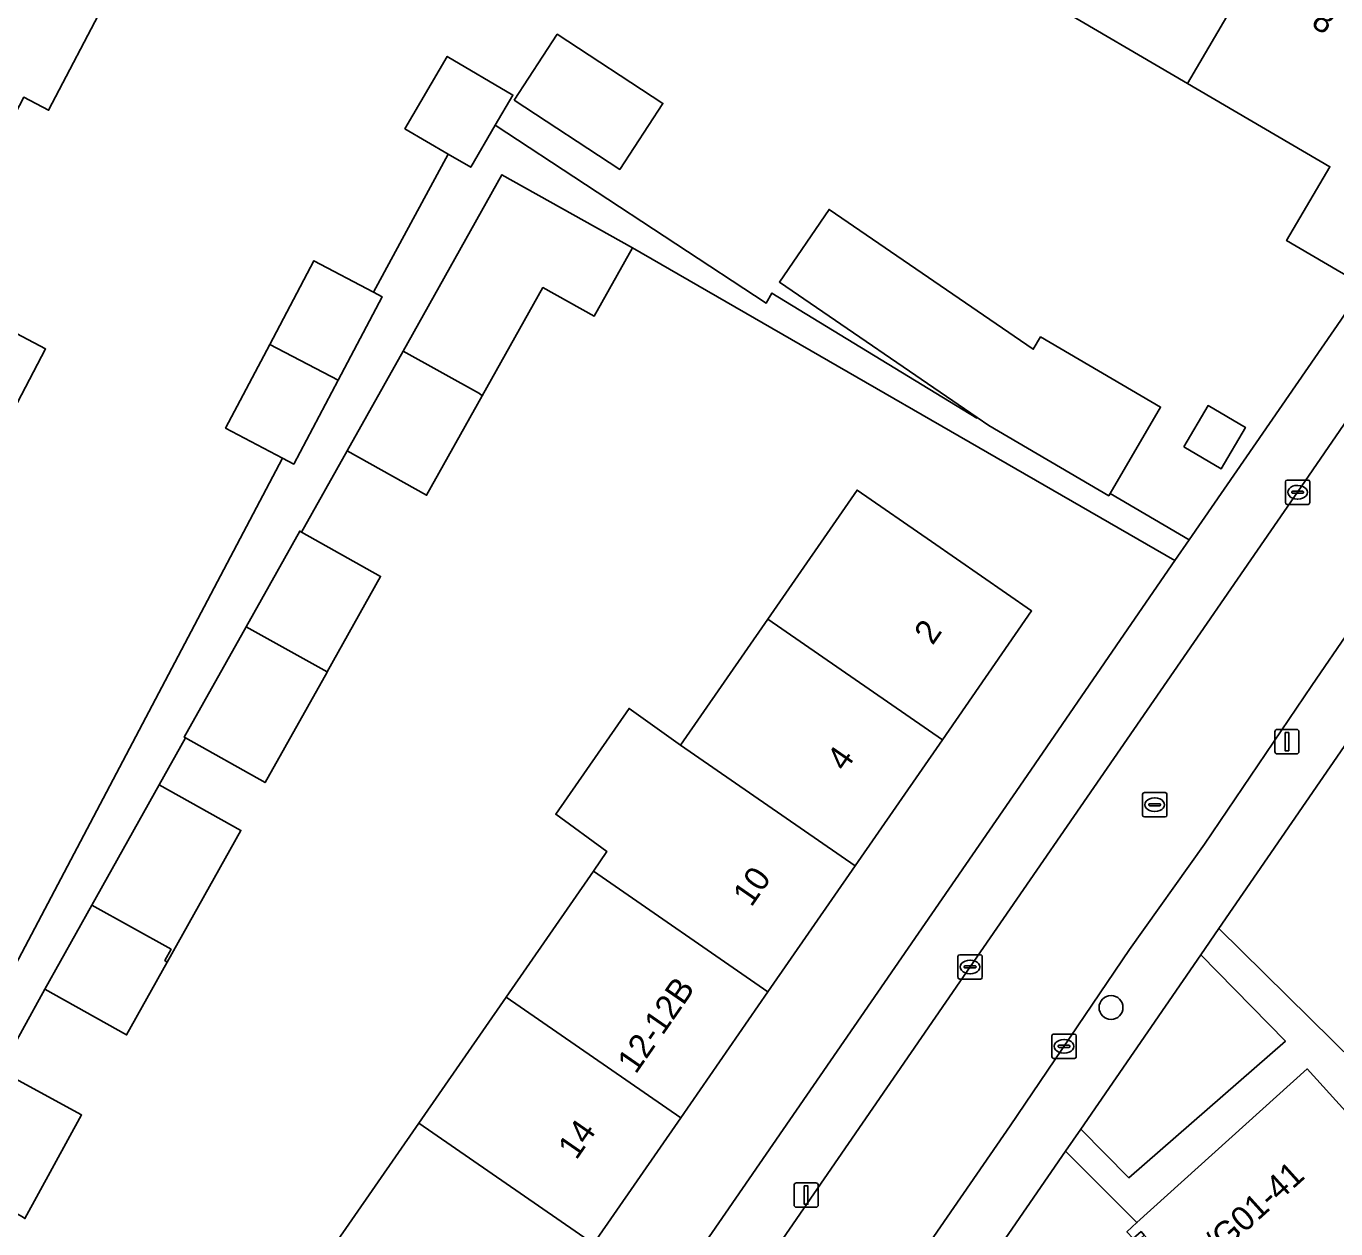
# Model space of a CAD drawing. Extents: x 160349 to 161355, y 381727 to 382854.
# Drawn here: x 160836.8 to 160890.5, y 382044.3 to 382093.6 of the extents above; entities that cross this region are included whole.
import ezdxf

# ---------------------------------------------------------------- set-up
doc = ezdxf.new("R2010")
doc.units = 0
for name, color, linetype in [('IMGEO_Boom', 7, 'Continuous'), ('IMGEO_Erf', 7, 'Continuous'), ('IMGEO_Groenvoorziening', 7, 'Continuous'), ('IMGEO_Kolk', 7, 'Continuous'), ('IMGEO_Lichtmast', 7, 'Continuous'), ('IMGEO_Pand', 7, 'Continuous'), ('IMGEO_Pand_nummerreeks', 7, 'Continuous'), ('IMGEO_Rijbaan_lokaal_open', 7, 'Continuous'), ('IMGEO_Rioolput', 7, 'Continuous'), ('IMGEO_Voetpad_open', 7, 'Continuous')]:
    doc.layers.add(name, color=color, linetype=linetype)

msp = doc.modelspace()

# ---------------------------------------------------------------- linework, layer by layer
at = {"layer": 'IMGEO_Boom'}
msp.add_circle((160881.263, 382053.407), 0.489, dxfattribs=at)
at = {"layer": 'IMGEO_Erf'}
for points in [[(160828.644, 382105.359), (160839.235, 382099.82), (160840.979, 382098.908), (160841.554, 382097.53), (160840.049, 382094.652), (160837.714, 382090.187), (160836.694, 382090.72)], [(160894.194, 382094.645), (160892.301, 382091.408), (160894.868, 382089.907), (160895.433, 382089.577), (160891.222, 382082.372), (160890.937, 382082.539), (160891.31, 382083.178), (160890.54, 382083.628), (160888.463, 382084.842), (160890.235, 382087.873), (160885.919, 382090.396), (160884.403, 382091.282), (160878.701, 382094.616)], [(160848.59, 382084.018), (160851.025, 382082.733), (160854.087, 382088.394), (160852.318, 382089.43), (160854.052, 382092.392), (160856.749, 382090.813), (160856.025, 382089.578), (160867.129, 382082.286), (160867.364, 382082.695), (160875.757, 382077.566), (160875.777, 382077.589), (160867.667, 382083.145), (160869.707, 382086.124), (160878.078, 382080.389), (160878.374, 382080.895), (160883.294, 382078.019), (160881.225, 382074.478), (160884.468, 382072.583), (160886.418, 382075.41), (160890.681, 382081.588), (160891.222, 382082.372), (160892.908, 382084.909), (160896.288, 382089.767), (160898.701, 382093.297)], [(160882.102, 382069.151), (160883.88, 382071.73), (160861.644, 382084.547), (160860.073, 382081.743), (160857.976, 382082.918), (160855.49, 382078.482), (160853.206, 382074.407), (160849.954, 382076.23), (160848.084, 382072.892), (160851.323, 382071.077), (160849.131, 382067.164), (160849.125, 382067.154), (160846.587, 382062.624), (160843.318, 382064.456), (160842.243, 382062.537), (160845.594, 382060.663), (160842.578, 382055.268), (160840.909, 382052.283), (160837.557, 382054.157), (160835.733, 382050.826), (160839.066, 382049.001), (160836.741, 382044.754)], [(160834.328, 382051.343), (160847.298, 382075.927), (160844.969, 382077.156), (160846.778, 382080.583), (160848.59, 382084.018)], [(160833.72, 382082.44), (160837.592, 382080.403), (160835.263, 382075.977)], [(160849.315, 382043.503), (160852.891, 382048.667), (160856.467, 382053.832), (160860.043, 382058.997), (160860.598, 382059.799), (160858.504, 382061.331), (160861.506, 382065.666), (160863.619, 382064.162), (160867.195, 382069.326), (160870.856, 382074.614), (160873.898, 382072.508), (160878.009, 382069.663), (160874.349, 382064.374), (160870.774, 382059.209), (160867.2, 382054.044), (160863.624, 382048.878), (160860.049, 382043.712)], [(160804.86, 381957.022), (160809.509, 381963.746), (160815.556, 381972.499), (160830.024, 381993.552), (160843.658, 382013.325), (160856.447, 382031.904), (160864.216, 382043.168), (160877.531, 382062.485), (160882.102, 382069.151)]]:
    msp.add_lwpolyline(points, dxfattribs=at)
for points in [[(160856.791, 382090.604), (160858.56, 382093.305), (160862.896, 382090.467), (160861.127, 382087.766)], [(160884.254, 382076.388), (160885.242, 382078.079), (160886.772, 382077.184), (160885.784, 382075.494)]]:
    msp.add_lwpolyline(points, close=True, dxfattribs=at)
at = {"layer": 'IMGEO_Groenvoorziening'}
for points in [[(160895.379, 382070.732), (160885.684, 382056.644), (160893.142, 382049.287)], [(160876.819, 382030.108), (160878.78, 382040.608), (160882.622, 382044.08), (160882.494, 382044.222), (160882.171, 382043.93), (160881.914, 382044.215), (160882.326, 382044.588), (160879.4, 382047.514), (160856.025, 382013.549), (160862.42, 382009.21), (160864.718, 382006.576), (160868.779, 382010.311), (160869.404, 382012.942), (160868.801, 382014.089), (160865.741, 382012.48), (160864.478, 382014.847)]]:
    msp.add_lwpolyline(points, dxfattribs=at)
msp.add_lwpolyline([(160881.997, 382046.425), (160888.414, 382052.033), (160884.945, 382055.57), (160880.026, 382048.423)], close=True, dxfattribs=at)
at = {"layer": 'IMGEO_Kolk'}
for p, q in [((160888.411, 382074.102), (160888.411, 382074.954)), ((160888.486, 382075.028), (160889.338, 382075.028)), ((160888.899, 382074.808), (160888.924, 382074.808)), ((160889.412, 382074.954), (160889.412, 382074.102)), ((160888.67, 382074.522), (160888.67, 382074.534)), ((160889.108, 382074.485), (160888.71, 382074.485)), ((160888.713, 382074.571), (160889.111, 382074.571)), ((160888.922, 382074.248), (160888.897, 382074.248)), ((160889.154, 382074.534), (160889.154, 382074.522)), ((160889.338, 382074.028), (160888.486, 382074.028)), ((160874.986, 382054.643), (160874.986, 382055.495)), ((160875.061, 382055.569), (160875.913, 382055.569)), ((160875.474, 382055.349), (160875.499, 382055.349)), ((160875.987, 382055.495), (160875.987, 382054.643)), ((160875.245, 382055.063), (160875.245, 382055.075)), ((160875.683, 382055.026), (160875.285, 382055.026)), ((160875.288, 382055.112), (160875.686, 382055.112)), ((160875.497, 382054.789), (160875.472, 382054.789)), ((160875.729, 382055.075), (160875.729, 382055.063)), ((160875.913, 382054.569), (160875.061, 382054.569)), ((160878.837, 382051.389), (160878.837, 382052.241)), ((160878.912, 382052.315), (160879.764, 382052.315)), ((160879.325, 382052.095), (160879.35, 382052.095)), ((160879.838, 382052.241), (160879.838, 382051.389)), ((160879.096, 382051.809), (160879.096, 382051.821)), ((160879.534, 382051.772), (160879.136, 382051.772)), ((160879.139, 382051.858), (160879.537, 382051.858)), ((160879.348, 382051.535), (160879.323, 382051.535)), ((160879.58, 382051.821), (160879.58, 382051.809)), ((160879.764, 382051.315), (160878.912, 382051.315))]:
    msp.add_line(p, q, dxfattribs=at)
for points in [[(160888.411, 382074.102), (160888.411, 382074.954)], [(160888.486, 382075.028), (160889.338, 382075.028)], [(160889.412, 382074.954), (160889.412, 382074.102)], [(160889.338, 382074.028), (160888.486, 382074.028)], [(160874.986, 382054.643), (160874.986, 382055.495)], [(160875.061, 382055.569), (160875.913, 382055.569)], [(160875.987, 382055.495), (160875.987, 382054.643)], [(160875.913, 382054.569), (160875.061, 382054.569)], [(160878.837, 382051.389), (160878.837, 382052.241)], [(160878.912, 382052.315), (160879.764, 382052.315)], [(160879.838, 382052.241), (160879.838, 382051.389)], [(160879.764, 382051.315), (160878.912, 382051.315)]]:
    msp.add_lwpolyline(points, dxfattribs=at)
for centre, radius, start, end in [((160888.488, 382074.952), 0.0765, 91.552, 178.448), ((160888.488, 382074.952), 0.0765, 91.552, 178.448), ((160889.336, 382074.952), 0.0765, 1.552, 88.448), ((160889.336, 382074.952), 0.0765, 1.552, 88.448), ((160888.488, 382074.104), 0.0765, 181.552, 268.448), ((160888.488, 382074.104), 0.0765, 181.552, 268.448), ((160888.71, 382074.531), 0.0403, 85.8775, 175.7526), ((160888.707, 382074.521), 0.0366, 178.938, 274.7102), ((160889.111, 382074.528), 0.043, 264.8664, 352.4533), ((160889.115, 382074.533), 0.0386, 1.7309, 96.639), ((160889.336, 382074.104), 0.0765, 271.552, 358.448), ((160889.336, 382074.104), 0.0765, 271.552, 358.448), ((160875.063, 382055.493), 0.0765, 91.552, 178.448), ((160875.063, 382055.493), 0.0765, 91.552, 178.448), ((160875.911, 382055.493), 0.0765, 1.552, 88.448), ((160875.911, 382055.493), 0.0765, 1.552, 88.448), ((160875.285, 382055.072), 0.0403, 85.8775, 175.7526), ((160875.282, 382055.062), 0.0366, 178.938, 274.7102), ((160875.686, 382055.069), 0.043, 264.8664, 352.4533), ((160875.69, 382055.074), 0.0386, 1.7309, 96.639), ((160875.063, 382054.645), 0.0765, 181.552, 268.448), ((160875.063, 382054.645), 0.0765, 181.552, 268.448), ((160875.911, 382054.645), 0.0765, 271.552, 358.448), ((160875.911, 382054.645), 0.0765, 271.552, 358.448), ((160878.914, 382052.239), 0.0765, 91.552, 178.448), ((160878.914, 382052.239), 0.0765, 91.552, 178.448), ((160879.762, 382052.239), 0.0765, 1.552, 88.448), ((160879.762, 382052.239), 0.0765, 1.552, 88.448), ((160879.136, 382051.818), 0.0403, 85.8775, 175.7526), ((160879.133, 382051.808), 0.0366, 178.938, 274.7102), ((160879.537, 382051.815), 0.043, 264.8664, 352.4533), ((160879.541, 382051.82), 0.0386, 1.7309, 96.639), ((160878.914, 382051.391), 0.0765, 181.552, 268.448), ((160878.914, 382051.391), 0.0765, 181.552, 268.448), ((160879.762, 382051.391), 0.0765, 271.552, 358.448), ((160879.762, 382051.391), 0.0765, 271.552, 358.448)]:
    msp.add_arc(centre, radius, start, end, dxfattribs=at)
for centre, major_axis, ratio, start_param, end_param in [((160888.898, 382074.528), (-0.387, 0.002), 0.722429, 4.712389, 7.853982), ((160888.923, 382074.528), (-0.39, 0.002), 0.717154, 1.570796, 4.712389), ((160875.473, 382055.069), (-0.387, 0.002), 0.722429, 4.712389, 7.853982), ((160875.498, 382055.069), (-0.39, 0.002), 0.717154, 1.570796, 4.712389), ((160879.324, 382051.815), (-0.387, 0.002), 0.722429, 4.712389, 7.853982), ((160879.349, 382051.815), (-0.39, 0.002), 0.717154, 1.570796, 4.712389)]:
    msp.add_ellipse(centre, major_axis=major_axis, ratio=ratio, start_param=start_param, end_param=end_param, dxfattribs=at)
at = {"layer": 'IMGEO_Lichtmast'}
for p, q in [((160887.978, 382063.904), (160887.978, 382064.704)), ((160887.978, 382064.704), (160887.978, 382063.904)), ((160888.078, 382064.804), (160888.868, 382064.804)), ((160888.868, 382064.804), (160888.078, 382064.804)), ((160888.968, 382064.704), (160888.968, 382063.904)), ((160888.968, 382063.904), (160888.968, 382064.704)), ((160888.868, 382063.804), (160888.078, 382063.804)), ((160888.078, 382063.804), (160888.868, 382063.804)), ((160868.37, 382046.216), (160869.16, 382046.216)), ((160869.16, 382046.216), (160868.37, 382046.216)), ((160868.27, 382045.316), (160868.27, 382046.116)), ((160868.27, 382046.116), (160868.27, 382045.316)), ((160869.26, 382046.116), (160869.26, 382045.316)), ((160869.26, 382045.316), (160869.26, 382046.116)), ((160869.16, 382045.216), (160868.37, 382045.216)), ((160868.37, 382045.216), (160869.16, 382045.216))]:
    msp.add_line(p, q, dxfattribs=at)
for points in [[(160888.398, 382064.679), (160888.548, 382064.679), (160888.548, 382063.929), (160888.398, 382063.929), (160888.398, 382064.679)], [(160868.69, 382046.091), (160868.84, 382046.091), (160868.84, 382045.341), (160868.69, 382045.341), (160868.69, 382046.091)]]:
    msp.add_lwpolyline(points, dxfattribs=at)
for centre, start, end in [((160888.078, 382064.704), 90, 180), ((160888.078, 382064.704), 90, 180), ((160888.868, 382064.704), 0, 90), ((160888.868, 382064.704), 360, 90), ((160888.078, 382063.904), 180, 270), ((160888.078, 382063.904), 180, 270), ((160888.868, 382063.904), 270, 0), ((160888.868, 382063.904), 270, 0), ((160868.37, 382046.116), 90, 180), ((160868.37, 382046.116), 90, 180), ((160869.16, 382046.116), 0, 90), ((160869.16, 382046.116), 360, 90), ((160868.37, 382045.316), 180, 270), ((160868.37, 382045.316), 180, 270), ((160869.16, 382045.316), 270, 0), ((160869.16, 382045.316), 270, 0)]:
    msp.add_arc(centre, 0.1, start, end, dxfattribs=at)
at = {"layer": 'IMGEO_Pand'}
for points in [[(160878.701, 382094.616), (160884.403, 382091.282), (160888.362, 382098.054), (160882.66, 382101.388)], [(160840.049, 382094.652), (160837.1, 382096.26), (160829.984, 382099.917), (160828.329, 382096.753), (160829.665, 382096.055), (160828.832, 382094.462), (160826.953, 382090.869), (160834.676, 382086.862), (160836.694, 382090.72), (160837.714, 382090.187)], [(160894.194, 382094.645), (160888.362, 382098.054), (160884.403, 382091.282), (160885.919, 382090.396), (160890.235, 382087.873), (160888.463, 382084.842), (160890.54, 382083.628), (160891.31, 382083.178), (160890.937, 382082.539), (160891.222, 382082.372), (160895.433, 382089.577), (160894.868, 382089.907), (160892.301, 382091.408)], [(160856.791, 382090.604), (160861.127, 382087.766), (160862.896, 382090.467), (160858.56, 382093.305)], [(160852.318, 382089.43), (160854.087, 382088.394), (160855.014, 382087.851), (160856.025, 382089.578), (160856.749, 382090.813), (160854.052, 382092.392)], [(160826.953, 382090.869), (160825.065, 382087.259), (160824.243, 382085.688), (160822.918, 382086.381), (160821.314, 382083.315), (160831.402, 382078.008), (160835.263, 382075.977), (160837.592, 382080.403), (160833.72, 382082.44), (160832.655, 382082.997), (160834.676, 382086.862)], [(160852.241, 382080.31), (160855.373, 382078.573), (160855.49, 382078.482), (160857.976, 382082.918), (160860.073, 382081.743), (160861.644, 382084.547), (160856.296, 382087.545)], [(160883.294, 382078.019), (160878.374, 382080.895), (160878.078, 382080.389), (160869.707, 382086.124), (160867.667, 382083.145), (160875.777, 382077.589), (160876.251, 382077.264), (160881.172, 382074.388), (160881.225, 382074.478)], [(160851.382, 382082.545), (160851.025, 382082.733), (160848.59, 382084.018), (160846.778, 382080.583), (160849.58, 382079.129)], [(160849.58, 382079.129), (160846.778, 382080.583), (160844.969, 382077.156), (160847.298, 382075.927), (160847.761, 382075.683)], [(160852.241, 382080.31), (160849.954, 382076.23), (160853.206, 382074.407), (160855.49, 382078.482), (160855.373, 382078.573)], [(160884.254, 382076.388), (160885.784, 382075.494), (160886.772, 382077.184), (160885.242, 382078.079)], [(160867.195, 382069.326), (160874.349, 382064.374), (160878.009, 382069.663), (160873.898, 382072.508), (160870.856, 382074.614)], [(160851.323, 382071.077), (160848.084, 382072.892), (160848.006, 382072.936), (160845.806, 382069.008), (160849.131, 382067.164)], [(160863.619, 382064.162), (160870.774, 382059.209), (160874.349, 382064.374), (160867.195, 382069.326)], [(160849.125, 382067.154), (160849.131, 382067.164), (160845.806, 382069.008), (160843.27, 382064.483), (160843.318, 382064.456), (160846.587, 382062.624)], [(160863.619, 382064.162), (160861.506, 382065.666), (160858.504, 382061.331), (160860.598, 382059.799), (160860.043, 382058.997), (160867.2, 382054.044), (160870.774, 382059.209)], [(160839.481, 382057.598), (160842.734, 382055.794), (160842.478, 382055.332), (160842.578, 382055.268), (160845.594, 382060.663), (160842.243, 382062.537)], [(160863.624, 382048.878), (160867.2, 382054.044), (160860.043, 382058.997), (160856.467, 382053.832)], [(160839.481, 382057.598), (160837.557, 382054.157), (160840.909, 382052.283), (160842.578, 382055.268), (160842.478, 382055.332), (160842.734, 382055.794)], [(160852.891, 382048.667), (160860.049, 382043.712), (160863.624, 382048.878), (160856.467, 382053.832)], [(160839.066, 382049.001), (160835.733, 382050.826), (160835.643, 382050.875), (160833.334, 382046.658), (160836.646, 382044.821), (160836.741, 382044.754)], [(160896.165, 382043.298), (160894.271, 382045.393), (160889.299, 382050.892), (160882.326, 382044.588), (160881.914, 382044.215), (160882.171, 382043.93), (160882.494, 382044.222), (160882.622, 382044.08), (160883.852, 382042.719), (160880.903, 382040.052), (160884.923, 382035.606), (160884.648, 382035.358), (160885.507, 382034.408), (160885.749, 382034.627), (160886.12, 382034.216), (160892.87, 382040.319)], [(160852.891, 382048.667), (160849.315, 382043.503), (160856.475, 382038.547), (160860.049, 382043.712)]]:
    msp.add_lwpolyline(points, close=True, dxfattribs=at)
at = {"layer": 'IMGEO_Rijbaan_lokaal_open'}
for points in [[(160900.454, 382091.336), (160898.732, 382088.827), (160897.579, 382087.17), (160888.911, 382074.534), (160875.487, 382055.069), (160862.667, 382036.458), (160849.849, 382017.829), (160838.733, 382001.705), (160827.599, 381985.555), (160816.487, 381969.406), (160806.996, 381955.65)], [(160863.124, 382028.242), (160864.448, 382030.182), (160867.631, 382034.676), (160871.484, 382040.355), (160873.174, 382042.828), (160877.127, 382048.557), (160882.027, 382055.784), (160885.092, 382060.107), (160889.498, 382066.61), (160894.202, 382073.493), (160902.442, 382085.568), (160903.558, 382087.228), (160905.012, 382089.324)]]:
    msp.add_lwpolyline(points, dxfattribs=at)
at = {"layer": 'IMGEO_Rioolput'}
for p, q in [((160882.554, 382061.293), (160882.554, 382062.145)), ((160882.629, 382062.219), (160883.481, 382062.219)), ((160882.813, 382061.713), (160882.813, 382061.725)), ((160882.856, 382061.762), (160883.254, 382061.762)), ((160883.042, 382061.999), (160883.067, 382061.999)), ((160883.297, 382061.725), (160883.297, 382061.713)), ((160883.555, 382062.145), (160883.555, 382061.293)), ((160883.481, 382061.219), (160882.629, 382061.219)), ((160883.251, 382061.676), (160882.853, 382061.676)), ((160883.065, 382061.439), (160883.04, 382061.439))]:
    msp.add_line(p, q, dxfattribs=at)
for points in [[(160882.554, 382061.293), (160882.554, 382062.145)], [(160882.629, 382062.219), (160883.481, 382062.219)], [(160883.555, 382062.145), (160883.555, 382061.293)], [(160883.481, 382061.219), (160882.629, 382061.219)]]:
    msp.add_lwpolyline(points, dxfattribs=at)
for centre, radius, start, end in [((160882.631, 382062.143), 0.0765, 91.552, 178.448), ((160882.631, 382062.143), 0.0765, 91.552, 178.448), ((160882.853, 382061.722), 0.0403, 85.8775, 175.7526), ((160883.258, 382061.724), 0.0386, 1.7309, 96.639), ((160883.479, 382062.143), 0.0765, 1.552, 88.448), ((160883.479, 382062.143), 0.0765, 1.552, 88.448), ((160882.631, 382061.295), 0.0765, 181.552, 268.448), ((160882.631, 382061.295), 0.0765, 181.552, 268.448), ((160882.85, 382061.712), 0.0366, 178.938, 274.7102), ((160883.254, 382061.719), 0.043, 264.8664, 352.4533), ((160883.479, 382061.295), 0.0765, 271.552, 358.448), ((160883.479, 382061.295), 0.0765, 271.552, 358.448)]:
    msp.add_arc(centre, radius, start, end, dxfattribs=at)
for centre, major_axis, ratio, start_param, end_param in [((160883.041, 382061.719), (-0.387, 0.002), 0.722429, 4.712389, 7.853982), ((160883.066, 382061.719), (-0.39, 0.002), 0.717154, 1.570796, 4.712389)]:
    msp.add_ellipse(centre, major_axis=major_axis, ratio=ratio, start_param=start_param, end_param=end_param, dxfattribs=at)
at = {"layer": 'IMGEO_Voetpad_open'}
for points in [[(160898.701, 382093.297), (160896.288, 382089.767), (160892.908, 382084.909), (160891.222, 382082.372), (160890.681, 382081.588), (160886.418, 382075.41), (160884.468, 382072.583), (160883.88, 382071.73), (160882.102, 382069.151), (160877.531, 382062.485), (160864.216, 382043.168), (160856.447, 382031.904), (160843.658, 382013.325), (160830.024, 381993.552), (160815.556, 381972.499), (160809.509, 381963.746)], [(160905.012, 382089.324), (160903.558, 382087.228), (160902.442, 382085.568), (160894.202, 382073.493), (160889.498, 382066.61), (160885.092, 382060.107), (160882.027, 382055.784), (160877.127, 382048.557), (160873.174, 382042.828), (160871.484, 382040.355), (160867.631, 382034.676), (160864.448, 382030.182), (160863.124, 382028.242), (160858.854, 382022.23), (160855.258, 382017.034), (160849.506, 382008.744), (160843.491, 382000), (160812.427, 381954.838), (160811.585, 381953.706)], [(160835.733, 382050.826), (160837.557, 382054.157), (160839.481, 382057.598), (160842.243, 382062.537), (160843.318, 382064.456), (160843.27, 382064.483), (160845.806, 382069.008), (160848.006, 382072.936), (160848.084, 382072.892), (160849.954, 382076.23), (160852.241, 382080.31), (160856.296, 382087.545), (160861.644, 382084.547), (160883.88, 382071.73), (160884.468, 382072.583), (160881.225, 382074.478), (160881.172, 382074.388), (160876.251, 382077.264), (160875.777, 382077.589), (160875.757, 382077.566), (160867.364, 382082.695), (160867.129, 382082.286), (160856.025, 382089.578), (160855.014, 382087.851), (160854.087, 382088.394), (160851.025, 382082.733), (160851.382, 382082.545), (160849.58, 382079.129), (160847.761, 382075.683), (160847.298, 382075.927), (160834.328, 382051.343)], [(160816.487, 381969.406), (160827.599, 381985.555), (160838.733, 382001.705), (160849.849, 382017.829), (160862.667, 382036.458), (160875.487, 382055.069), (160888.911, 382074.534), (160897.579, 382087.17)], [(160879.4, 382047.514), (160880.026, 382048.423), (160884.945, 382055.57), (160885.684, 382056.644), (160895.379, 382070.732), (160897.798, 382071.659), (160908.103, 382086.516)], [(160893.142, 382049.287), (160885.684, 382056.644), (160884.945, 382055.57), (160888.414, 382052.033), (160881.997, 382046.425), (160880.026, 382048.423), (160879.4, 382047.514), (160882.326, 382044.588), (160889.299, 382050.892), (160894.271, 382045.393)], [(160815.016, 381954.084), (160820.18, 381961.222), (160821.136, 381962.535), (160825.506, 381968.975), (160826.232, 381970.197), (160846.705, 382000), (160849.898, 382004.648), (160850.803, 382005.961), (160855.241, 382012.41), (160856.025, 382013.549), (160879.4, 382047.514)]]:
    msp.add_lwpolyline(points, dxfattribs=at)

# ---------------------------------------------------------------- texts
at = {"layer": 'IMGEO_Pand_nummerreeks'}
for s, rotation, p in [('8', 329.6905, (160889.421, 382093.637)), ('2', 55.3143, (160873.949, 382068.225)), ('4', 55.3173, (160870.362, 382063.04)), ('10', 55.3153, (160866.518, 382057.489)), ('12-12B', 55.3143, (160861.781, 382050.643)), ('14', 55.3143, (160859.346, 382047.124)), ('35/G01-41', 42.1181, (160884.574, 382042.198))]:
    msp.add_text(s, height=1, rotation=rotation, dxfattribs=at).set_placement(p)

doc.saveas('drawing.dxf')
